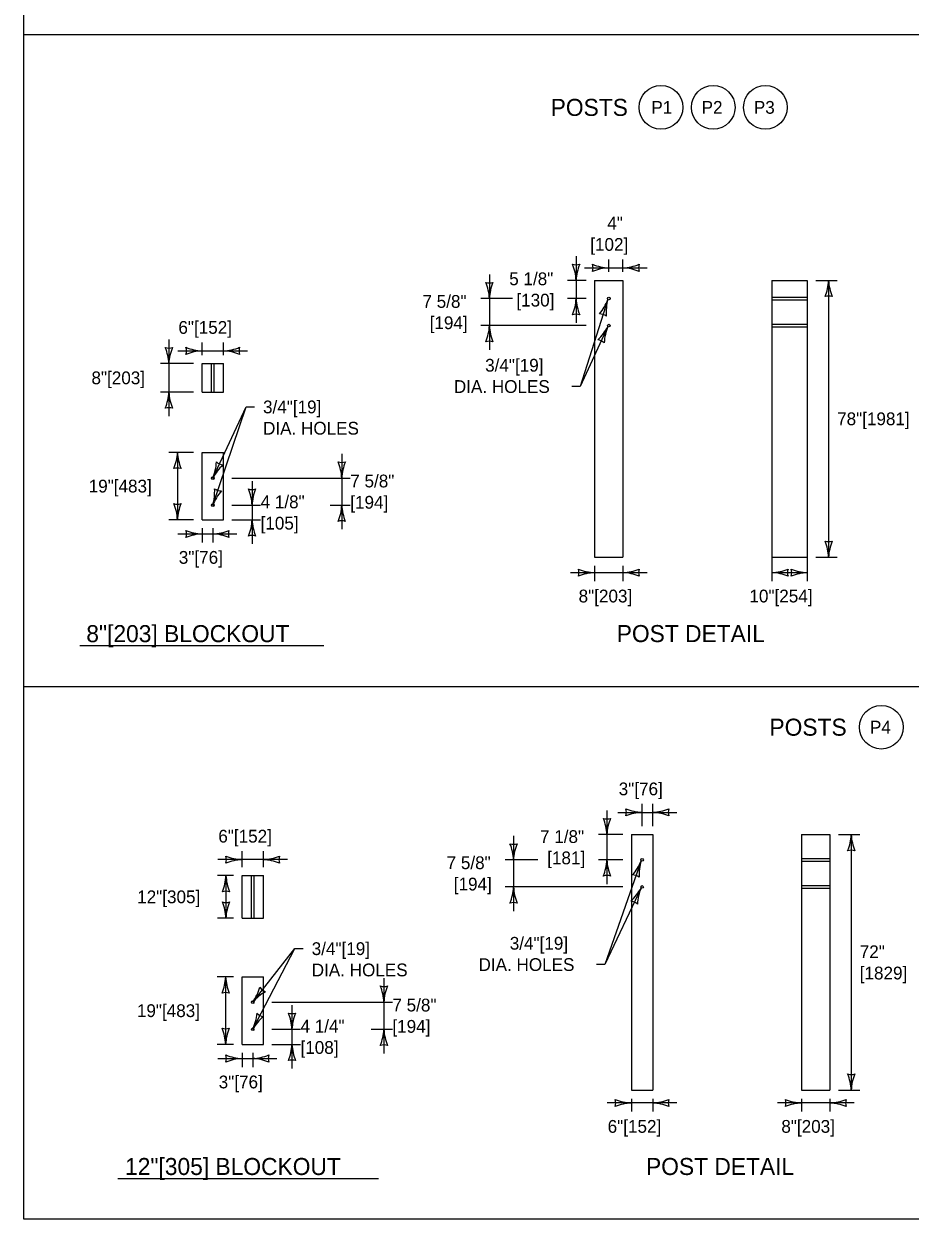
# Model space of a CAD drawing. Extents: x 49991 to 50160, y 49948 to 50051.
# Drawn here: x 49999.38 to 50003.54, y 49987.8 to 49993.41 of the extents above; entities that cross this region are included whole.
import ezdxf

# ---------------------------------------------------------------- set-up
doc = ezdxf.new("R2010")
doc.units = 0
for name, color, linetype in [('Level 1', 7, 'Continuous'), ('Level 2', 7, 'Continuous'), ('Level 3', 7, 'Continuous'), ('Level 4', 7, 'Continuous')]:
    doc.layers.add(name, color=color, linetype=linetype)

msp = doc.modelspace()

# ---------------------------------------------------------------- linework, layer by layer
at = {"layer": 'Level 1'}
for p, q in [((50002.063, 49992.2059), (50002.063, 49990.9059)), ((50002.063, 49992.2059), (50002.1964, 49992.2059)), ((50002.1964, 49992.2059), (50002.1964, 49990.9059)), ((50002.8954, 49992.2059), (50002.8954, 49990.9059)), ((50002.8954, 49992.2059), (50003.0621, 49992.2059)), ((50003.0621, 49992.2059), (50003.0621, 49990.9059)), ((50000.2204, 49991.6816), (50000.2204, 49991.815)), ((50000.2204, 49991.815), (50000.3204, 49991.815)), ((50000.3204, 49991.6816), (50000.3204, 49991.815)), ((50000.2204, 49991.6816), (50000.3204, 49991.6816)), ((50000.2204, 49991.0818), (50000.2204, 49991.3984)), ((50000.2204, 49991.3984), (50000.3204, 49991.3984)), ((50000.3204, 49991.0818), (50000.3204, 49991.3984)), ((50000.2204, 49991.0818), (50000.3204, 49991.0818)), ((50002.063, 49990.9059), (50002.1964, 49990.9059)), ((50002.8954, 49990.9059), (50003.0621, 49990.9059)), ((49999.3835, 49990.2991), (50008.1103, 49990.2991)), ((50002.236, 49989.604), (50002.236, 49988.404)), ((50002.236, 49989.604), (50002.336, 49989.604)), ((50002.336, 49989.604), (50002.336, 49988.404)), ((50003.035, 49989.604), (50003.035, 49988.404)), ((50003.035, 49989.604), (50003.1683, 49989.604)), ((50003.1683, 49989.604), (50003.1683, 49988.404)), ((50000.4078, 49989.2117), (50000.4078, 49989.4117)), ((50000.4078, 49989.4117), (50000.5078, 49989.4117)), ((50000.5078, 49989.2117), (50000.5078, 49989.4117)), ((50000.4078, 49989.2117), (50000.5078, 49989.2117)), ((50000.4078, 49988.619), (50000.4078, 49988.9356)), ((50000.4078, 49988.9356), (50000.5078, 49988.9356)), ((50000.5078, 49988.619), (50000.5078, 49988.9356)), ((50000.4078, 49988.619), (50000.5078, 49988.619)), ((50002.236, 49988.404), (50002.336, 49988.404)), ((50003.035, 49988.404), (50003.1684, 49988.404))]:
    msp.add_line(p, q, dxfattribs=at)
msp.add_lwpolyline([(49999.3835, 49998.9992), (50016.7501, 49998.9992), (50016.7501, 49987.7988), (49999.3835, 49987.7988)], close=True, dxfattribs=at)
msp.add_lwpolyline([(50006.1377, 49990.2991), (50006.1377, 49993.358), (49999.3835, 49993.358)], dxfattribs=at)
for centre in [(50002.1297, 49992.1204), (50002.1297, 49991.9934), (50000.2704, 49991.2776), (50000.2704, 49991.1505), (50002.286, 49989.4852), (50002.286, 49989.3581), (50000.4578, 49988.8169), (50000.4578, 49988.6898)]:
    msp.add_circle(centre, 0.00625, dxfattribs=at)
at = {"layer": 'Level 2'}
for p, q in [((49999.6467, 49990.4914), (50000.7913, 49990.4914)), ((49999.8246, 49987.9898), (50001.0491, 49987.9898))]:
    msp.add_line(p, q, dxfattribs=at)
for centre in [(50002.3749, 49993.018), (50002.6202, 49993.018), (50002.8655, 49993.018), (50003.4096, 49990.1082)]:
    msp.add_circle(centre, 0.1026, dxfattribs=at)
at = {"layer": 'Level 3'}
for p, q in [((50001.9765, 49992.3193), (50001.9765, 49992.007)), ((50002.1297, 49992.2459), (50002.1297, 49992.3046)), ((50002.1964, 49992.2459), (50002.1964, 49992.3046)), ((50001.5692, 49992.2339), (50001.5692, 49991.8799)), ((50002.0163, 49992.2646), (50002.3098, 49992.2646)), ((50002.023, 49992.2059), (50001.9365, 49992.2059)), ((50003.1021, 49992.2059), (50003.2021, 49992.2059)), ((50003.1621, 49992.2059), (50003.1621, 49990.9059)), ((50001.6771, 49992.1204), (50001.5292, 49992.1204)), ((50002.023, 49992.1204), (50001.9365, 49992.1204)), ((50002.1253, 49992.116), (50001.9959, 49991.7074)), ((50002.023, 49991.9934), (50001.5292, 49991.9934)), ((50002.1253, 49991.9889), (50001.9959, 49991.7074)), ((50000.0642, 49991.9284), (50000.0642, 49991.5682)), ((50000.2204, 49991.855), (50000.2204, 49991.915)), ((50000.3204, 49991.855), (50000.3204, 49991.915)), ((50000.107, 49991.875), (50000.4339, 49991.875)), ((50000.1804, 49991.815), (50000.0242, 49991.815)), ((50000.1804, 49991.6816), (50000.0242, 49991.6816)), ((50001.9959, 49991.7074), (50001.9559, 49991.7074)), ((50000.2704, 49991.2776), (50000.4264, 49991.6117)), ((50000.2704, 49991.1505), (50000.4264, 49991.6117)), ((50000.4264, 49991.6117), (50000.4664, 49991.6117)), ((50000.1804, 49991.3984), (50000.0646, 49991.3984)), ((50000.1046, 49991.3984), (50000.1046, 49991.0818)), ((50000.876, 49991.391), (50000.876, 49991.0371)), ((50000.3604, 49991.2776), (50000.916, 49991.2776)), ((50000.4549, 49991.2639), (50000.4549, 49990.9683)), ((50000.3604, 49991.1505), (50000.4949, 49991.1505)), ((50000.8217, 49991.1505), (50000.916, 49991.1505)), ((50000.1804, 49991.0818), (50000.0646, 49991.0818)), ((50000.3604, 49991.0818), (50000.4949, 49991.0818)), ((50000.107, 49991.0154), (50000.3839, 49991.0154)), ((50000.2204, 49991.0418), (50000.2204, 49990.9754)), ((50000.2704, 49991.0418), (50000.2704, 49990.9754)), ((50000.4549, 49991.006), (50000.4549, 49990.986)), ((50002.8954, 49990.9059), (50002.8954, 49990.8659)), ((50003.0621, 49990.9059), (50003.0621, 49990.8659)), ((50003.1021, 49990.9059), (50003.2021, 49990.9059)), ((50001.9496, 49990.8339), (50002.3098, 49990.8339)), ((50002.063, 49990.8659), (50002.063, 49990.7939)), ((50002.1964, 49990.8659), (50002.1964, 49990.7939)), ((50002.8954, 49990.8659), (50002.8954, 49990.7939)), ((50002.8954, 49990.8339), (50003.0621, 49990.8339)), ((50003.0621, 49990.8659), (50003.0621, 49990.7939)), ((50002.1211, 49989.7174), (50002.1211, 49989.3718)), ((50002.1726, 49989.7084), (50002.4495, 49989.7084)), ((50002.286, 49989.644), (50002.286, 49989.7484)), ((50002.336, 49989.644), (50002.336, 49989.7484)), ((50001.6826, 49989.5987), (50001.6826, 49989.2447)), ((50002.196, 49989.604), (50002.0811, 49989.604)), ((50003.2083, 49989.604), (50003.3083, 49989.604)), ((50003.2683, 49989.604), (50003.2683, 49988.404)), ((50000.6212, 49989.4864), (50000.2944, 49989.4864)), ((50000.4078, 49989.4517), (50000.4078, 49989.5264)), ((50000.5078, 49989.4517), (50000.5078, 49989.5264)), ((50001.7961, 49989.4852), (50001.6426, 49989.4852)), ((50002.196, 49989.4852), (50002.0811, 49989.4852)), ((50002.2816, 49989.4808), (50002.1116, 49988.9937)), ((50000.3678, 49989.4117), (50000.2923, 49989.4117)), ((50000.3323, 49989.4117), (50000.3323, 49989.2117)), ((50002.196, 49989.3581), (50001.6426, 49989.3581)), ((50002.2816, 49989.3537), (50002.1116, 49988.9937)), ((50000.3678, 49989.2117), (50000.2923, 49989.2117)), ((50000.4578, 49988.6898), (50000.655, 49989.0685)), ((50000.4578, 49988.8169), (50000.655, 49989.0685)), ((50000.655, 49989.0685), (50000.695, 49989.0685)), ((50002.1116, 49988.9937), (50002.0716, 49988.9937)), ((50000.3678, 49988.9356), (50000.2909, 49988.9356)), ((50000.3309, 49988.9356), (50000.3309, 49988.619)), ((50001.0739, 49988.9306), (50001.0739, 49988.5766)), ((50000.5478, 49988.8171), (50001.1139, 49988.8171)), ((50000.6423, 49988.8035), (50000.6423, 49988.5055)), ((50000.5478, 49988.69), (50000.6823, 49988.69)), ((50001.0146, 49988.69), (50001.1139, 49988.69)), ((50000.3678, 49988.619), (50000.2909, 49988.619)), ((50000.4078, 49988.579), (50000.4078, 49988.5126)), ((50000.4578, 49988.579), (50000.4578, 49988.5126)), ((50000.5478, 49988.619), (50000.6823, 49988.619)), ((50000.2944, 49988.5526), (50000.5712, 49988.5526)), ((50000.6422, 49988.5455), (50000.6422, 49988.5055)), ((50002.236, 49988.364), (50002.236, 49988.304)), ((50002.336, 49988.364), (50002.336, 49988.304)), ((50003.035, 49988.364), (50003.035, 49988.304)), ((50003.1683, 49988.364), (50003.1683, 49988.304)), ((50003.2083, 49988.404), (50003.3083, 49988.404)), ((50002.4495, 49988.344), (50002.1226, 49988.344)), ((50003.2818, 49988.344), (50002.9216, 49988.344))]:
    msp.add_line(p, q, dxfattribs=at)
for centre, radius, start, end in [((50001.9765, 49992.3341), 0.0548, 252.1388, 287.8612), ((50001.7438, 49992.1944), 0.233, 2.8273, 22.0772), ((50002.1986, 49992.1967), 0.2223, 157.456, 177.6395), ((50002.1389, 49992.4867), 0.2223, 247.456, 267.6395), ((50002.0015, 49992.2646), 0.0548, 342.1388, 17.8612), ((50002.1849, 49992.4973), 0.233, 272.8273, 292.0772), ((50002.3246, 49992.2646), 0.0548, 162.1388, 197.8612), ((50002.1412, 49992.0319), 0.233, 92.8273, 112.0772), ((50002.1872, 49992.0425), 0.2223, 67.456, 87.6395), ((50001.5692, 49992.2487), 0.0548, 252.1388, 287.8612), ((50001.3365, 49992.109), 0.233, 2.8273, 22.0772), ((50001.7913, 49992.1113), 0.2223, 157.456, 177.6395), ((50002.9399, 49992.215), 0.2223, 337.456, 357.6395), ((50003.3948, 49992.2174), 0.233, 182.8273, 202.0772), ((50001.7544, 49992.1296), 0.2223, 337.456, 357.6395), ((50002.2092, 49992.1319), 0.233, 182.8273, 202.0772), ((50001.9163, 49992.1918), 0.2223, 319.8824, 340.0659), ((50002.3506, 49992.0567), 0.233, 165.2537, 184.5036), ((50003.1621, 49992.0777), 0.0548, 72.1388, 107.8612), ((50001.9765, 49991.9922), 0.0548, 72.1388, 107.8612), ((50002.0866, 49991.9938), 0.0548, 54.5652, 90.2876), ((50001.347, 49992.0025), 0.2223, 337.456, 357.6395), ((50001.8019, 49992.0049), 0.233, 182.8273, 202.0772), ((50001.9273, 49992.09), 0.2223, 312.7704, 332.954), ((50002.3415, 49991.9022), 0.233, 158.1417, 177.3916), ((50000.0642, 49991.9432), 0.0548, 252.1388, 287.8612), ((49999.8315, 49991.8035), 0.233, 2.8273, 22.0772), ((50000.2863, 49991.8058), 0.2223, 157.456, 177.6395), ((50000.2296, 49992.0971), 0.2223, 247.456, 267.6395), ((50000.0922, 49991.875), 0.0548, 342.1388, 17.8612), ((50000.309, 49992.1077), 0.233, 272.8273, 292.0772), ((50000.4487, 49991.875), 0.0548, 162.1388, 197.8612), ((50001.5692, 49991.8651), 0.0548, 72.1388, 107.8612), ((50002.0717, 49991.8724), 0.0548, 47.4533, 83.1756), ((50000.2319, 49991.6423), 0.233, 92.8273, 112.0772), ((50000.3113, 49991.6528), 0.2223, 67.456, 87.6395), ((49999.842, 49991.6908), 0.2223, 337.456, 357.6395), ((50000.2969, 49991.6931), 0.233, 182.8273, 202.0772), ((50000.0642, 49991.5534), 0.0548, 72.1388, 107.8612), ((49999.8825, 49991.4076), 0.2223, 337.456, 357.6395), ((50000.3373, 49991.4099), 0.233, 182.8273, 202.0772), ((50000.0547, 49991.3656), 0.233, 337.8064, 357.0563), ((50000.4679, 49991.1753), 0.2223, 132.4351, 152.6186), ((50000.3247, 49991.3938), 0.0548, 227.1179, 262.8403), ((50000.876, 49991.4058), 0.0548, 252.1388, 287.8612), ((50000.6433, 49991.2661), 0.233, 2.8273, 22.0772), ((50001.0982, 49991.2684), 0.2223, 157.456, 177.6395), ((50000.1046, 49991.2702), 0.0548, 72.1388, 107.8612), ((50000.0463, 49991.2142), 0.233, 344.1454, 3.3953), ((50000.4779, 49991.0707), 0.2223, 138.7741, 158.9576), ((50000.3115, 49991.272), 0.0548, 233.4569, 269.1793), ((50000.4549, 49991.2787), 0.0548, 252.1388, 287.8612), ((50000.2222, 49991.139), 0.233, 2.8273, 22.0772), ((50000.677, 49991.1413), 0.2223, 157.456, 177.6395), ((50000.1046, 49991.21), 0.0548, 252.1388, 287.8612), ((49999.8719, 49991.0703), 0.233, 2.8273, 22.0772), ((50000.3268, 49991.0726), 0.2223, 157.456, 177.6395), ((50000.6539, 49991.1597), 0.2223, 337.456, 357.6395), ((50001.1087, 49991.162), 0.233, 182.8273, 202.0772), ((50000.2328, 49991.0909), 0.2223, 337.456, 357.6395), ((50000.6876, 49991.0932), 0.233, 182.8273, 202.0772), ((50000.876, 49991.0223), 0.0548, 72.1388, 107.8612), ((50000.2296, 49991.2375), 0.2223, 247.456, 267.6395), ((50000.0922, 49991.0154), 0.0548, 342.1388, 17.8612), ((50000.2319, 49990.7827), 0.233, 92.8273, 112.0772), ((50000.259, 49991.2481), 0.233, 272.8273, 292.0772), ((50000.2613, 49990.7932), 0.2223, 67.456, 87.6395), ((50000.3987, 49991.0154), 0.0548, 162.1388, 197.8612), ((50000.4549, 49990.9535), 0.0548, 72.1388, 107.8612), ((50003.1621, 49991.0341), 0.0548, 252.1388, 287.8612), ((50002.9294, 49990.8944), 0.233, 2.8273, 22.0772), ((50003.3842, 49990.8967), 0.2223, 157.456, 177.6395), ((50002.0722, 49991.056), 0.2223, 247.456, 267.6395), ((50001.9348, 49990.8339), 0.0548, 342.1388, 17.8612), ((50002.0745, 49990.6011), 0.233, 92.8273, 112.0772), ((50002.1849, 49991.0666), 0.233, 272.8273, 292.0772), ((50002.1872, 49990.6117), 0.2223, 67.456, 87.6395), ((50002.3246, 49990.8339), 0.0548, 162.1388, 197.8612), ((50002.8839, 49991.0666), 0.233, 272.8273, 292.0772), ((50002.8862, 49990.6117), 0.2223, 67.456, 87.6395), ((50003.0236, 49990.8339), 0.0548, 162.1388, 197.8612), ((50003.0712, 49991.056), 0.2223, 247.456, 267.6395), ((50002.9339, 49990.8339), 0.0548, 342.1388, 17.8612), ((50003.0736, 49990.6011), 0.233, 92.8273, 112.0772), ((50002.2952, 49989.9305), 0.2223, 247.456, 267.6395), ((50002.1578, 49989.7084), 0.0548, 342.1388, 17.8612), ((50002.2975, 49989.4757), 0.233, 92.8273, 112.0772), ((50002.3245, 49989.9411), 0.233, 272.8273, 292.0772), ((50002.3269, 49989.4862), 0.2223, 67.456, 87.6395), ((50002.4642, 49989.7084), 0.0548, 162.1388, 197.8612), ((50002.1211, 49989.7322), 0.0548, 252.1388, 287.8612), ((50001.8884, 49989.5925), 0.233, 2.8273, 22.0772), ((50002.3432, 49989.5948), 0.2223, 157.456, 177.6395), ((50003.0462, 49989.6131), 0.2223, 337.456, 357.6395), ((50003.501, 49989.6155), 0.233, 182.8273, 202.0772), ((50001.6826, 49989.6134), 0.0548, 252.1388, 287.8612), ((50001.4499, 49989.4737), 0.233, 2.8273, 22.0772), ((50001.9047, 49989.4761), 0.2223, 157.456, 177.6395), ((50003.2683, 49989.4758), 0.0548, 72.1388, 107.8612), ((50000.417, 49989.7085), 0.2223, 247.456, 267.6395), ((50000.2796, 49989.4864), 0.0548, 342.1388, 17.8612), ((50000.4193, 49989.2537), 0.233, 92.8273, 112.0772), ((50000.4963, 49989.7191), 0.233, 272.8273, 292.0772), ((50000.4986, 49989.2642), 0.2223, 67.456, 87.6395), ((50000.636, 49989.4864), 0.0548, 162.1388, 197.8612), ((50001.8989, 49989.4944), 0.2223, 337.456, 357.6395), ((50002.3538, 49989.4967), 0.233, 182.8273, 202.0772), ((50002.0749, 49989.5627), 0.2223, 318.2144, 338.3979), ((50002.5051, 49989.415), 0.233, 163.5857, 182.8356), ((50000.1102, 49989.4208), 0.2223, 337.456, 357.6395), ((50000.565, 49989.4232), 0.233, 182.8273, 202.0772), ((50002.1211, 49989.357), 0.0548, 72.1388, 107.8612), ((50002.2393, 49989.3597), 0.0548, 52.8972, 88.6196), ((50000.3323, 49989.2834), 0.0548, 72.1388, 107.8612), ((50001.4604, 49989.3673), 0.2223, 337.456, 357.6395), ((50001.9153, 49989.3696), 0.233, 182.8273, 202.0772), ((50002.0846, 49989.4569), 0.2223, 312.1767, 332.3602), ((50002.4969, 49989.2647), 0.233, 157.548, 176.7979), ((50000.3323, 49989.3399), 0.0548, 252.1388, 287.8612), ((50000.0996, 49989.2002), 0.233, 2.8273, 22.0772), ((50000.5544, 49989.2025), 0.2223, 157.456, 177.6395), ((50001.6826, 49989.2299), 0.0548, 72.1388, 107.8612), ((50002.2268, 49989.2378), 0.0548, 46.8595, 82.5819), ((50000.1088, 49988.9448), 0.2223, 337.456, 357.6395), ((50000.5636, 49988.9471), 0.233, 182.8273, 202.0772), ((50000.3309, 49988.8074), 0.0548, 72.1388, 107.8612), ((50000.2675, 49988.9514), 0.233, 324.7487, 343.9985), ((50000.627, 49988.6727), 0.2223, 119.3774, 139.5609), ((50000.5369, 49988.9178), 0.0548, 214.0602, 249.7826), ((50001.0739, 49988.9454), 0.0548, 252.1388, 287.8612), ((50000.8412, 49988.8056), 0.233, 2.8273, 22.0772), ((50001.296, 49988.808), 0.2223, 157.456, 177.6395), ((50000.2461, 49988.7871), 0.233, 335.3275, 354.5773), ((50000.6506, 49988.5791), 0.2223, 129.9562, 150.1397), ((50000.517, 49988.8035), 0.0548, 224.639, 260.3613), ((50000.6423, 49988.8183), 0.0548, 252.1388, 287.8612), ((50000.4095, 49988.6785), 0.233, 2.8273, 22.0772), ((50000.8644, 49988.6809), 0.2223, 157.456, 177.6395), ((50000.3309, 49988.7472), 0.0548, 252.1388, 287.8612), ((50000.0982, 49988.6075), 0.233, 2.8273, 22.0772), ((50000.553, 49988.6098), 0.2223, 157.456, 177.6395), ((50000.8517, 49988.6992), 0.2223, 337.456, 357.6395), ((50001.3066, 49988.7015), 0.233, 182.8273, 202.0772), ((50000.4201, 49988.6281), 0.2223, 337.456, 357.6395), ((50000.875, 49988.6305), 0.233, 182.8273, 202.0772), ((50001.0739, 49988.5618), 0.0548, 72.1388, 107.8612), ((50000.417, 49988.7747), 0.2223, 247.456, 267.6395), ((50000.2796, 49988.5526), 0.0548, 342.1388, 17.8612), ((50000.4193, 49988.3199), 0.233, 92.8273, 112.0772), ((50000.4463, 49988.7853), 0.233, 272.8273, 292.0772), ((50000.4486, 49988.3305), 0.2223, 67.456, 87.6395), ((50000.586, 49988.5526), 0.0548, 162.1388, 197.8612), ((50000.6423, 49988.4908), 0.0548, 72.1388, 107.8612), ((50003.2683, 49988.5322), 0.0548, 252.1388, 287.8612), ((50003.0356, 49988.3925), 0.233, 2.8273, 22.0772), ((50003.4904, 49988.3948), 0.2223, 157.456, 177.6395), ((50002.2452, 49988.5661), 0.2223, 247.456, 267.6395), ((50002.1078, 49988.344), 0.0548, 342.1388, 17.8612), ((50002.3245, 49988.5767), 0.233, 272.8273, 292.0772), ((50002.4642, 49988.344), 0.0548, 162.1388, 197.8612), ((50003.0442, 49988.5661), 0.2223, 247.456, 267.6395), ((50002.9068, 49988.344), 0.0548, 342.1388, 17.8612), ((50003.1569, 49988.5767), 0.233, 272.8273, 292.0772), ((50003.2966, 49988.344), 0.0548, 162.1388, 197.8612), ((50002.2475, 49988.1113), 0.233, 92.8273, 112.0772), ((50002.3269, 49988.1218), 0.2223, 67.456, 87.6395), ((50003.0465, 49988.1113), 0.233, 92.8273, 112.0772), ((50003.1592, 49988.1218), 0.2223, 67.456, 87.6395)]:
    msp.add_arc(centre, radius, start, end, dxfattribs=at)
at = {"layer": 'Level 4'}
for p, q in [((50002.8954, 49992.1267), (50003.0621, 49992.1267)), ((50002.8954, 49992.1142), (50003.0621, 49992.1142)), ((50002.8954, 49991.9996), (50003.0621, 49991.9996)), ((50002.8954, 49991.9871), (50003.0621, 49991.9871)), ((50000.2642, 49991.6816), (50000.2642, 49991.815)), ((50000.2767, 49991.6816), (50000.2767, 49991.815)), ((50003.035, 49989.4915), (50003.1683, 49989.4915)), ((50003.035, 49989.479), (50003.1683, 49989.479)), ((50000.4516, 49989.2117), (50000.4516, 49989.4117)), ((50000.4641, 49989.2117), (50000.4641, 49989.4117)), ((50003.035, 49989.3644), (50003.1683, 49989.3644)), ((50003.035, 49989.3519), (50003.1683, 49989.3519))]:
    msp.add_line(p, q, dxfattribs=at)

# ---------------------------------------------------------------- texts
at = {"layer": 'Level 2'}
for s, height, p in [('POSTS', 0.08, (50001.857, 49992.978)), ('P1', 0.06, (50002.3298, 49992.988)), ('P2', 0.06, (50002.5658, 49992.9881)), ('P3', 0.06, (50002.811, 49992.9881)), ('4"', 0.06, (50002.1227, 49992.4446)), ('[102]', 0.06, (50002.0428, 49992.3446)), ('5 1/8"', 0.06, (50001.6624, 49992.1832)), ('7 5/8"', 0.06, (50001.255, 49992.0769)), ('[130]', 0.06, (50001.6961, 49992.0832)), ('6"[152]', 0.06, (50000.109, 49991.955)), ('[194]', 0.06, (50001.2887, 49991.9769)), ('3/4"[19]', 0.06, (50001.5493, 49991.7774)), ('8"[203]', 0.06, (49999.7008, 49991.7183)), ('DIA. HOLES', 0.06, (50001.4025, 49991.6774)), ('3/4"[19]', 0.06, (50000.5064, 49991.5817)), ('78"[1981]', 0.06, (50003.2021, 49991.5259)), ('DIA. HOLES', 0.06, (50000.5064, 49991.4817)), ('19"[483]', 0.06, (49999.6878, 49991.2101)), ('7 5/8"', 0.06, (50000.916, 49991.234)), ('4 1/8"', 0.06, (50000.4949, 49991.1361)), ('[194]', 0.06, (50000.916, 49991.134)), ('[105]', 0.06, (50000.4949, 49991.0361)), ('3"[76]', 0.06, (50000.1109, 49990.8754)), ('8"[203]', 0.06, (50001.9883, 49990.6939)), ('10"[254]', 0.06, (50002.7903, 49990.6939)), ('8"[203] BLOCKOUT', 0.08, (49999.6766, 49990.5074)), ('POST DETAIL', 0.08, (50002.1672, 49990.5077)), ('POSTS', 0.08, (50002.8843, 49990.0682)), ('P4', 0.06, (50003.3565, 49990.0784)), ('3"[76]', 0.06, (50002.1765, 49989.7884)), ('6"[152]', 0.06, (50000.2964, 49989.5664)), ('7 1/8"', 0.06, (50001.8069, 49989.5646)), ('7 5/8"', 0.06, (50001.3684, 49989.4417)), ('[181]', 0.06, (50001.8406, 49989.4646)), ('[194]', 0.06, (50001.4021, 49989.3417)), ('12"[305]', 0.06, (49999.9155, 49989.2817)), ('3/4"[19]', 0.06, (50000.735, 49989.0385)), ('3/4"[19]', 0.06, (50001.665, 49989.0637)), ('72"', 0.06, (50003.3083, 49989.024)), ('DIA. HOLES', 0.06, (50001.5182, 49988.9637)), ('DIA. HOLES', 0.06, (50000.735, 49988.9385)), ('[1829]', 0.06, (50003.3083, 49988.924)), ('19"[483]', 0.06, (49999.9141, 49988.7473)), ('7 5/8"', 0.06, (50001.1139, 49988.7736)), ('4 1/4"', 0.06, (50000.6823, 49988.6745)), ('[194]', 0.06, (50001.1139, 49988.6736)), ('[108]', 0.06, (50000.6823, 49988.5745)), ('3"[76]', 0.06, (50000.2983, 49988.4126)), ('6"[152]', 0.06, (50002.1246, 49988.204)), ('8"[203]', 0.06, (50002.9402, 49988.204)), ('12"[305] BLOCKOUT', 0.08, (49999.8585, 49988.0058)), ('POST DETAIL', 0.08, (50002.3047, 49988.0058))]:
    msp.add_text(s, height=height, dxfattribs=at).set_placement(p)

doc.saveas('drawing.dxf')
